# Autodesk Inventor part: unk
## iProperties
Author: Dave Hoder
Shininess: 64.0
Angle Display Precision: 2
Document Length Units: 11272
Document Angle Units: 11286
Document Time Units: 11279
Document Mass Units: 11290
Document Length Units Precision: 3
Document Angle Units Precision: 2
Compacted: True
PropertySet Name: _Private Model Information
Created: 2001-12
Part Number: unk
Material: Steel, Mild
Description: T-Nut 3/8-16
Document SubType Name: Modeling
Designer: Dave Hoder
Control State: 0
Master: False
Checked Out: False
PropertySet Name: Design Tracking Control
Density: 7.86
Volumn: 0.7053388263478713
Area: 10.765166503059744
PropertySet Name: Model Information
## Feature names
1. Revolution1
2. Barb [Extrusion]
3. Circular Pattern1
